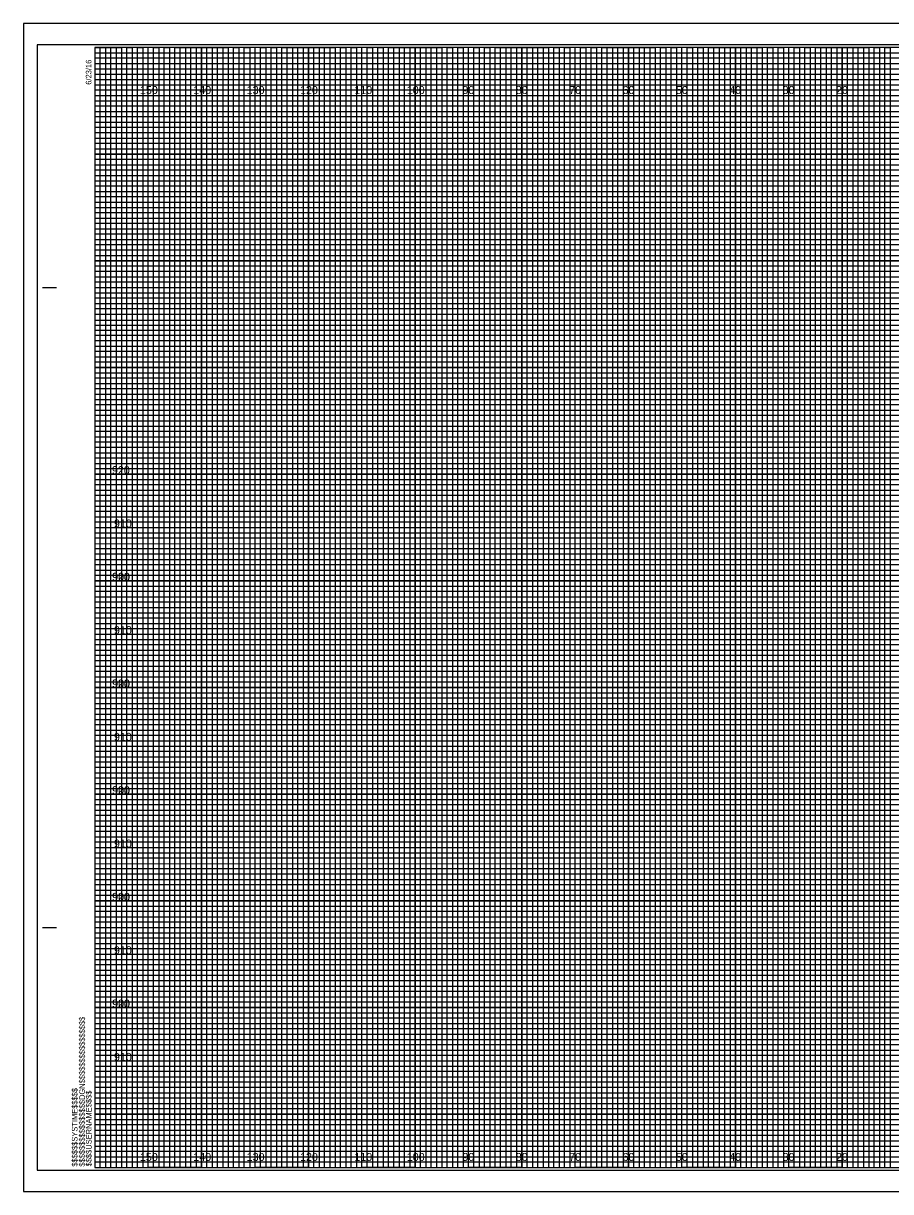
# Model space of a CAD drawing. Extents: x -13 to 323, y -4 to 214.
# Drawn here: x -13.4 to 149.1, y -4.5 to 214.5 of the extents above; entities that cross this region are included whole.
import ezdxf

# ---------------------------------------------------------------- set-up
doc = ezdxf.new("R2010")
doc.units = 0
for name, color, linetype in [('Prop XS Elevation Labels', 7, 'Continuous'), ('Prop XS Offset Labels', 7, 'Continuous'), ('Sheet Cross Section CELL', 7, 'Continuous'), ('Sheet Cross Section Grid Major CELL', 7, 'Continuous'), ('Sheet Cross Section Grid Middle CELL', 7, 'Continuous'), ('Sheet Cross Section Grid Minor 1 CELL', 7, 'Continuous'), ('Sheet Cross Section Grid Minor 2 CELL', 7, 'Continuous'), ('Sheet Cutting Line CELL', 7, 'Continuous'), ('Sheet DOT Grid CELL', 7, 'Continuous'), ('Sheet Plot Border Inside CELL', 7, 'Continuous'), ('Sheet Plot Border Outside CELL', 7, 'Continuous')]:
    doc.layers.add(name, color=color, linetype=linetype)

msp = doc.modelspace()

# ---------------------------------------------------------------- linework, layer by layer
at = {"layer": 'Sheet Cross Section CELL'}
for p, q in [((-9.8, 165), (-7.3, 165)), ((-9.7, 165), (-7.2, 165)), ((-9.8, 45), (-7.3, 45)), ((-9.7, 45), (-7.2, 45)), ((0, 0), (0, 0)), ((0, 0), (0, 0)), ((0, 0), (0, 0)), ((0, 0), (0, 0)), ((0, 0), (0, 0)), ((0, 0), (0, 0)), ((0, 0), (0, 0))]:
    msp.add_line(p, q, dxfattribs=at)
msp.add_lwpolyline([(320, 210), (0, 210), (0, 0), (320, 0)], close=True, dxfattribs=at)
at = {"layer": 'Sheet Cross Section Grid Major CELL'}
for p, q in [((10, 210), (0, 210)), ((10, 0), (10, 210)), ((30, 210), (20, 210)), ((20, 210), (20, 0)), ((30, 0), (30, 210)), ((50, 210), (40, 210)), ((40, 210), (40, 0)), ((50, 0), (50, 210)), ((70, 210), (60, 210)), ((60, 210), (60, 0)), ((70, 0), (70, 210)), ((90, 210), (80, 210)), ((80, 210), (80, 0)), ((90, 0), (90, 210)), ((110, 210), (100, 210)), ((100, 210), (100, 0)), ((110, 0), (110, 210)), ((130, 210), (120, 210)), ((120, 210), (120, 0)), ((130, 0), (130, 210)), ((150, 210), (140, 210)), ((140, 210), (140, 0)), ((20, 0), (10, 0)), ((40, 0), (30, 0)), ((60, 0), (50, 0)), ((80, 0), (70, 0)), ((100, 0), (90, 0)), ((120, 0), (110, 0)), ((140, 0), (130, 0))]:
    msp.add_line(p, q, dxfattribs=at)
for points in [[(0, 200), (320, 200), (320, 190), (0, 190)], [(0, 180), (320, 180), (320, 170), (0, 170)], [(0, 160), (320, 160), (320, 150), (0, 150)], [(0, 140), (320, 140), (320, 130), (0, 130)], [(0, 120), (320, 120), (320, 110), (0, 110)], [(0, 100), (320, 100), (320, 90), (0, 90)], [(0, 80), (320, 80), (320, 70), (0, 70)], [(0, 60), (320, 60), (320, 50), (0, 50)], [(0, 40), (320, 40), (320, 30), (0, 30)], [(0, 20), (320, 20), (320, 10), (0, 10)]]:
    msp.add_lwpolyline(points, dxfattribs=at)
at = {"layer": 'Sheet Cross Section Grid Middle CELL'}
for points in [[(0, 210), (5, 210), (5, 0), (15, 0), (15, 210), (25, 210), (25, 0), (35, 0), (35, 210), (45, 210), (45, 0), (55, 0), (55, 210), (65, 210), (65, 0), (75, 0), (75, 210), (85, 210), (85, 0), (95, 0), (95, 210), (105, 210), (105, 0), (115, 0), (115, 210), (125, 210), (125, 0), (135, 0), (135, 210), (145, 210), (145, 0), (155, 0)], [(0, 205), (275, 205)], [(0, 185), (320, 185), (320, 195), (0, 195)], [(0, 165), (320, 165), (320, 175), (0, 175)], [(0, 145), (320, 145), (320, 155), (0, 155)], [(0, 125), (320, 125), (320, 135), (0, 135)], [(0, 105), (320, 105), (320, 115), (0, 115)], [(0, 85), (320, 85), (320, 95), (0, 95)], [(0, 65), (320, 65), (320, 75), (0, 75)], [(0, 45), (320, 45), (320, 55), (0, 55)], [(0, 25), (320, 25), (320, 35), (0, 35)], [(0, 5), (320, 5), (320, 15), (0, 15)]]:
    msp.add_lwpolyline(points, dxfattribs=at)
at = {"layer": 'Sheet Cross Section Grid Minor 1 CELL'}
for p, q in [((0, 209), (260, 209)), ((260, 207.98), (0, 207.98)), ((0, 207.98), (0, 207)), ((0, 207), (260, 207)), ((260, 205.89), (0, 205.89)), ((0, 205.89), (0, 204)), ((0, 204), (320, 204))]:
    msp.add_line(p, q, dxfattribs=at)
for points in [[(0, 203), (270, 203), (320, 203), (320, 202), (0, 202)], [(0, 201), (320, 201), (320, 199), (0, 199)], [(0, 198), (320, 198), (320, 197), (0, 196.98)], [(0, 196), (320, 196), (320, 194), (0, 194)], [(0, 193), (320, 193), (320, 192), (0, 192)], [(0, 191), (320, 191), (320, 189), (0, 189)], [(0, 188), (320, 188), (320, 187), (0, 187)], [(0, 186), (320, 186), (320, 184), (0, 184)], [(0, 183), (320, 183), (320, 182), (0, 182)], [(0, 181), (320, 181), (320, 179), (0, 179)], [(0, 178), (320, 178), (320, 177), (0, 177)], [(0, 176), (320, 176), (320, 173.95), (320, 173), (320, 172), (0, 172)], [(0, 174), (320, 174), (320, 173), (0, 173)], [(0, 171), (320, 171), (320, 169), (0, 169.03)], [(0, 169.03), (320, 169), (320, 168), (0, 168)], [(0, 167), (320, 167), (320, 166), (0, 166)], [(0, 164), (320, 164), (320, 163), (0, 163)], [(0, 162), (320, 162), (320, 161), (0, 161)], [(-0.07, 158.89), (320, 158.89), (320, 157.88), (-0.07, 157.88)], [(0, 157), (320, 157), (320, 156), (0, 156)], [(0, 154), (320, 154), (320, 153), (0, 153)], [(0, 152), (320, 152), (320, 151), (0, 151)], [(0, 149), (320, 149), (320, 148), (0, 148)], [(0, 147), (320, 147), (320, 146), (0, 146)], [(0, 144), (320, 144), (320, 143), (0, 143)], [(0, 142), (320, 142), (320, 141), (0, 141)], [(0, 139), (320, 139), (319.99, 137.98), (0, 138)], [(0, 137), (320, 137), (320, 136), (0, 136)], [(0, 134), (320, 134), (320, 133), (0, 133)], [(0, 132), (320, 132), (320, 131), (0, 131)], [(0, 129), (320, 129), (320, 128), (0, 128)], [(0, 127), (320, 127), (320, 126), (0, 126)], [(0, 124), (320, 124), (320, 123), (0, 123)], [(0, 122), (320, 122), (320, 121), (0, 121)], [(0, 119), (320, 119), (320, 118), (0, 118)], [(0, 116.99), (320.07, 116.91), (320, 116), (0, 116)], [(0, 114), (320, 114), (320, 113), (0, 113)], [(0, 112), (320, 112), (320, 111), (0, 111)], [(0, 109), (320, 109), (320, 108), (0, 108)], [(0, 107), (320, 107), (320, 106), (0, 106)], [(0, 104), (320, 104), (320, 103), (0, 103)], [(0, 102), (320, 102), (320, 101), (0, 101)], [(0, 99), (320, 99), (320, 98), (0, 98)], [(0, 97), (320, 97), (320, 96), (0, 96)], [(0, 94), (320, 94), (320, 93), (0, 93)], [(0, 92), (320, 92), (320, 91), (0, 91)], [(0, 89), (320, 89), (320, 88), (0, 88)], [(0, 87), (320, 87), (320, 86), (0, 86)], [(0, 84), (320, 84), (320, 83), (0, 83)], [(0, 82), (320, 82), (320, 81), (0, 81)], [(0, 79), (320, 79), (319.99, 77.98), (0, 78)], [(0, 77), (320, 77), (320, 76), (0, 76)], [(0, 74), (320, 74), (320, 73), (0, 73)], [(0, 72), (320, 72), (320, 71), (0, 71)], [(0, 69), (320, 69), (320, 68), (0, 68)], [(0, 67), (320, 67), (320, 66), (0, 66)], [(0, 64), (320, 64), (320, 63), (0, 63)], [(0, 62), (320, 62), (320, 61), (0, 61)], [(0, 59), (320, 59), (320, 58), (0, 58)], [(0, 56.99), (320.07, 56.91), (320, 56), (0, 56)], [(0, 54), (320, 54), (320, 53), (0, 53)], [(0, 52), (320, 52), (320, 51), (0, 51)], [(0, 49), (320, 49), (320, 48), (0, 48)], [(0, 47), (320, 47), (320, 46), (0, 46)], [(0, 44), (320, 44), (320, 43), (0, 43)], [(0, 42), (320, 42), (320, 41), (0, 41)], [(0, 39), (320, 39), (320, 38), (0, 38)], [(0, 37), (320, 37), (320, 36), (0, 36)], [(0, 34), (320, 34), (320, 33), (0, 33)], [(0, 32), (320, 32), (320, 31), (0, 31)], [(0, 29), (320, 29), (320, 28), (0, 28)], [(0, 27), (320, 27), (320, 26), (0, 26)], [(0, 24), (320, 24), (320, 23), (0, 23)], [(0, 22), (320, 22), (320, 21), (0, 21)], [(0, 19), (320, 19), (320, 18), (0, 18)], [(0, 17), (320, 17), (320, 16), (0, 16)], [(0, 14), (320, 14), (320, 13), (0, 13)], [(0, 12), (320, 12), (320, 11), (0, 11)], [(0, 9), (320, 9), (320, 8), (0, 8)], [(0, 7), (320, 7), (320, 6), (0, 6)], [(0, 4), (320, 4), (320, 3), (0, 3)], [(0, 2), (320, 2), (320, 1), (0, 1)]]:
    msp.add_lwpolyline(points, dxfattribs=at)
at = {"layer": 'Sheet Cross Section Grid Minor 2 CELL'}
for points in [[(0, 0), (1, 0), (1, 210), (2, 210), (2, 0)], [(2, 0), (3, 0), (3, 210), (4, 210), (4, 0)], [(5, 0), (6, 0), (6, 210), (7, 210), (7, 0)], [(7, 0), (8, 0), (8, 210), (9, 210), (9, 0)], [(10, 0), (11, 0), (11, 210), (12, 210), (12, 0)], [(12, 0), (13, 0), (13, 210), (14, 210), (14, 0)], [(15, 0), (16, 0), (16, 210), (17, 210), (17, 0)], [(17, 0), (18, 0), (18, 210), (19, 210), (19, 0)], [(20, 0), (21, 0), (21, 210), (22, 210), (22, 0)], [(22, 0), (23, 0), (23, 210), (24, 210), (24, 0)], [(25, 0), (26, 0), (26, 210), (27, 210), (27, 0)], [(27, 0), (28, 0), (28, 210), (29, 210), (29, 0)], [(30, 0), (31, 0), (31, 210), (32, 210), (32, 0)], [(32, 0), (33, 0), (33, 210), (34, 210), (34, 0)], [(35, 0), (36, 0), (36, 210), (37, 210), (37, 0)], [(37, 0), (38, 0), (38, 210), (39, 210), (39, 0)], [(40, 0), (41, 0), (41, 210), (42, 210), (42, 0)], [(42, 0), (43, 0), (43, 210), (44, 210), (44, 0)], [(45, 0), (46, 0), (46, 210), (47, 210), (47, 0)], [(47, 0), (48, 0), (48, 210), (49, 210), (49, 0)], [(50, 0), (51, 0), (51, 210), (52, 210), (52, 0)], [(52, 0), (53, 0), (53, 210), (54, 210), (54, 0)], [(55, 0), (56, 0), (56, 210), (57, 210), (57, 0)], [(57, 0), (58, 0), (58, 210), (59, 210), (59, 0)], [(60, 0), (61, 0), (61, 210), (62, 210), (62, 0)], [(62, 0), (63, 0), (63, 210), (64, 210), (64, 0)], [(65, 0), (66, 0), (66, 210), (67, 210), (67, 0)], [(67, 0), (68, 0), (68, 210), (69, 210), (69, 0)], [(70, 0), (71, 0), (71, 210), (72, 210), (72, 0)], [(72, 0), (73, 0), (73, 210), (74, 210), (74, 0)], [(75, 0), (76, 0), (76, 210), (77, 210), (77, 0)], [(77, 0), (78, 0), (78, 210), (79, 210), (79, 0)], [(80, 0), (81, 0), (81, 210), (82, 210), (82, 0)], [(82, 0), (83, 0), (83, 210), (84, 210), (84, 0)], [(85, 0), (86, 0), (86, 210), (87, 210), (87, 0)], [(87, 0), (88, 0), (88, 210), (89, 210), (89, 0)], [(90, 0), (91, 0), (91, 210), (92, 210), (92, 0)], [(92, 0), (93, 0), (93, 210), (94, 210), (94, 0)], [(95, 0), (96, 0), (96, 210), (97, 210), (97, 0)], [(97, 0), (98, 0), (98, 210), (99, 210), (99, 0)], [(100, 0), (101, 0), (101, 210), (102, 210), (102, 0)], [(102, 0), (103, 0), (103, 210), (104, 210), (104, 0)], [(105, 0), (106, 0), (106, 210), (107, 210), (107, 0)], [(107, 0), (108, 0), (108, 210), (109, 210), (109, 0)], [(110, 0), (111, 0), (111, 210), (112, 210), (112, 0)], [(112, 0), (113, 0), (113, 210), (114, 210), (114, 0)], [(115, 0), (116, 0), (116, 210), (117, 210), (117, 0)], [(117, 0), (118, 0), (118, 210), (119, 210), (119, 0)], [(120, 0), (121, 0), (121, 210), (122, 210), (122, 0)], [(122, 0), (123, 0), (123, 210), (124, 210), (124, 0)], [(125, 0), (126, 0), (126, 210), (127, 210), (127, 0)], [(127, 0), (128, 0), (128, 210), (129, 210), (129, 0)], [(130, 0), (131, 0), (131, 210), (132, 210), (132, 0)], [(132, 0), (133, 0), (133, 210), (134, 210), (134, 0)], [(135, 0), (136, 0), (136, 210), (137, 210), (137, 0)], [(137, 0), (138, 0), (138, 210), (139, 210), (139, 0)], [(140, 0), (141, 0), (141, 210), (142, 210), (142, 0)], [(142, 0), (143, 0), (143, 210), (144, 210), (144, 0)], [(145, 0), (146, 0), (146, 210), (147, 210), (147, 0)], [(147, 0), (148, 0), (148, 210), (149, 210), (149, 0)]]:
    msp.add_lwpolyline(points, dxfattribs=at)
at = {"layer": 'Sheet Cutting Line CELL'}
for p, q in [((323.3, 214.5), (-13.4, 214.5)), ((-13.4, 214.5), (-13.4, -4.5)), ((-13.4, -4.5), (323.3, -4.5))]:
    msp.add_line(p, q, dxfattribs=at)
at = {"layer": 'Sheet DOT Grid CELL'}
for p, q in [((10, 0), (10, 210)), ((20, 0), (20, 210)), ((30, 0), (30, 210)), ((40, 0), (40, 210)), ((50, 0), (50, 210)), ((60, 0), (60, 210)), ((70, 0), (70, 210)), ((80, 0), (80, 210)), ((90, 0), (90, 210)), ((100, 0), (100, 210)), ((110, 0), (110, 210)), ((120, 0), (120, 210)), ((130, 0), (130, 210)), ((140, 0), (140, 210)), ((0, 200), (320, 200)), ((0, 190), (320, 190)), ((0, 180), (320, 180)), ((0, 170), (320, 170)), ((0, 160), (320, 160)), ((0, 150), (320, 150)), ((0, 140), (320, 140)), ((0, 130), (320, 130)), ((0, 120), (320, 120)), ((0, 110), (320, 110)), ((0, 100), (320, 100)), ((0, 90), (320, 90)), ((0, 80), (320, 80)), ((0, 70), (320, 70)), ((0, 60), (320, 60)), ((0, 50), (320, 50)), ((0, 40), (320, 40)), ((0, 30), (320, 30)), ((0, 20), (320, 20)), ((0, 10), (320, 10))]:
    msp.add_line(p, q, dxfattribs=at)
at = {"layer": 'Sheet Plot Border Inside CELL'}
msp.add_lwpolyline([(-10.8, -0.5), (322.4, -0.5), (322.4, 210.5), (-10.8, 210.5)], close=True, dxfattribs=at)
at = {"layer": 'Sheet Plot Border Outside CELL'}
msp.add_lwpolyline([(-13.4, -4.5), (323.3, -4.5), (323.3, 214.5), (-13.4, 214.5)], close=True, dxfattribs=at)

# ---------------------------------------------------------------- texts
at = {"layer": 'Prop XS Elevation Labels'}
for s, p in [('920', (3.19, 130)), ('910', (3.57, 120)), ('920', (3.19, 110)), ('900', (3.24, 110)), ('910', (3.57, 100)), ('920', (3.19, 90)), ('900', (3.24, 90)), ('910', (3.57, 80)), ('920', (3.19, 70)), ('900', (3.24, 70)), ('910', (3.57, 60)), ('920', (3.19, 50)), ('900', (3.24, 50)), ('910', (3.57, 40)), ('920', (3.19, 30)), ('900', (3.24, 30)), ('910', (3.57, 20))]:
    msp.add_text(s, height=1.5, dxfattribs=at).set_placement(p)
at = {"layer": 'Prop XS Offset Labels'}
for s, p in [('150', (8.44, 201.25)), ('140', (18.44, 201.25)), ('130', (28.44, 201.25)), ('120', (38.44, 201.25)), ('110', (48.62, 201.25)), ('100', (58.44, 201.25)), ('90', (68.86, 201.25)), ('80', (78.86, 201.25)), ('70', (88.86, 201.25)), ('60', (98.86, 201.25)), ('50', (108.86, 201.25)), ('40', (118.86, 201.25)), ('30', (128.86, 201.25)), ('20', (138.86, 201.25)), ('150', (8.44, 1.25)), ('140', (18.44, 1.25)), ('130', (28.44, 1.25)), ('120', (38.44, 1.25)), ('110', (48.62, 1.25)), ('100', (58.44, 1.25)), ('90', (68.86, 1.25)), ('80', (78.86, 1.25)), ('70', (88.86, 1.25)), ('60', (98.86, 1.25)), ('50', (108.86, 1.25)), ('40', (118.86, 1.25)), ('30', (128.86, 1.25)), ('20', (138.86, 1.25))]:
    msp.add_text(s, height=1.5, dxfattribs=at).set_placement(p)
at = {"layer": 'Sheet Cross Section CELL'}
for s, p in [('6/23/16', (-0.65, 203)), ('$$$$$$$$$$$$$$$$DGN$$$$$$$$$$$$$$$$', (-1.88, 0.18)), ('$$$$$$SYSTIME$$$$$', (-3.26, 0.18)), ('$$$$USERNAME$$$$', (-0.62, 0.23))]:
    msp.add_text(s, height=1.05, rotation=90, dxfattribs=at).set_placement(p)

doc.saveas('drawing.dxf')
